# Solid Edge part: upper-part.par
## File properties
Author: Vicky Raina
Template: Part8.par
Last saved by: MYPC
Revision: 2
Application: Solid Edge
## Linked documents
Part8.par
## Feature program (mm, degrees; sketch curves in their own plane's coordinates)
part copy "unnamed PartCopy 1"
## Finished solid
Body 1: solid body, 23 faces, 60 edges, 40 vertices.
  Faces by surface: plane 9, cylinder 8, sphere 4, torus 2
  Edges by curve: circle 32, line 22, intersection 6
Bounding box of the edges (mm; curved faces can reach further): 68.011 x 85.812 x 33.994, from (-34.0057, -34, 0) to (34.0057, 51.8118, 33.994).
Cylindrical faces by radius (mm): R2.5 x4, R3 x1, R10.5 x1, R12.5 x2
Toroidal faces (ring radius, tube radius in mm): R-32.4919 r64.4976 x1, R-32.4919 r66.4976 x1
Spherical faces by radius (mm): R22 x1, R24 x1, R32 x1, R34 x1
Planar faces by outward normal: +y 3, -y 3, -z 3
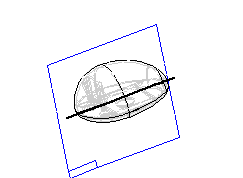
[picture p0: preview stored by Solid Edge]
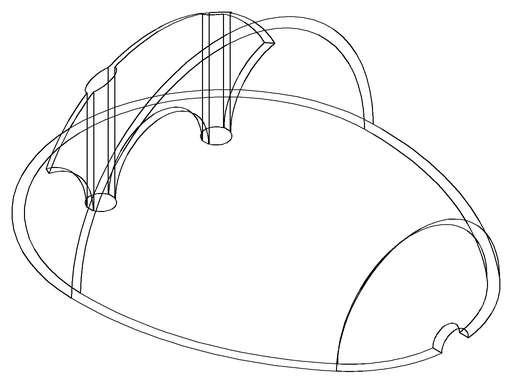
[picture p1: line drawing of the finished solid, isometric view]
